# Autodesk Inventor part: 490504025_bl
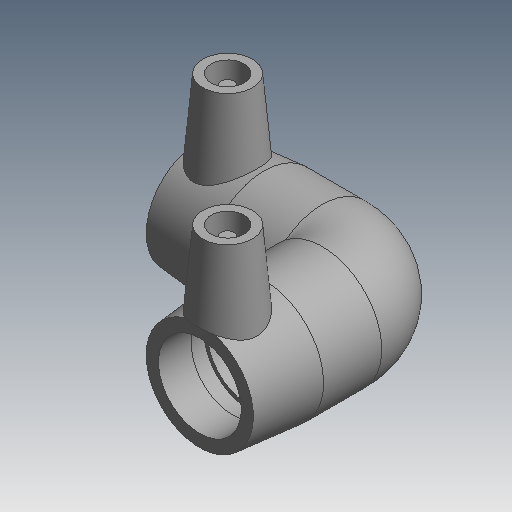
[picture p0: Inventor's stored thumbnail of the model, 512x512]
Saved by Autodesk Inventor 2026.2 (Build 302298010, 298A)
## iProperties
Created: 2017-06
Part Number: 490504025_bl
Material: Generic
Description: PLASSON 90° ELBOW 25
Document SubType Name: Modeling
Designer: KIM
Mass: 55.0731 g
Surface Area: 148.067 cm^2
Volume: 55.0731 cm^3
Density: 1 g/cm^3
Appearance: Default
Author: KIM
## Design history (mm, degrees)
derived "490504 -20-75.ipt"
feature "Solid1::490504 -20-75.ipt" dims "ScaleForDerivedMember" = 10
tag "TaggingFeature1"
body "Solid1"
other parameters: "d2" = 36 [user parameter], "d4" = 19.41176 [user parameter], "d5" = 32.4 [user parameter], "d8" = 168 deg [user parameter], "d10" = 14.8 [user parameter], "d11" = 4.93333 [user parameter], "d14" = 17.6296 [user parameter], "d18" = 25 [user parameter], "d19" = 3.52592 [user parameter], "d20" = 168 deg [user parameter], "d22" = 33.12 [user parameter], "d23" = 36 [user parameter], "d24" = 32.1264 [user parameter], "d29" = 38 [user parameter], "d30" = 15 [user parameter], "d31" = 39.6 [user parameter], "d34" = 5 deg [user parameter], "d35" = 15 [user parameter], "d39" = 5 deg [user parameter], "d41" = 4 [user parameter], "d42" = 14 [user parameter], "d43" = 0 [user parameter], "d45" = 4 [user parameter], "d46" = 14 [user parameter], "d47" = 0 [user parameter], "d49" = 25 [user parameter], "d50" = 21.25 [user parameter], "d51" = 14.8 [user parameter], "d52" = 37 [user parameter], "d54" = 90 deg [user parameter], "d65" = 25 [user parameter], "d67" = 45 deg [user parameter], "d71" = 90 deg [user parameter], "d75" = 1.8 [user parameter], "d82" = 45 deg [user parameter], "d83" = 37 [user parameter], "d84" = 32.4 [user parameter], "d87" = 90 deg [user parameter], "d90" = 37 [user parameter], "d91" = 0 [user parameter], "d92" = 37 [user parameter], "d93" = 0 [user parameter], "d94" = 90 deg [user parameter], "d101" = 3 [user parameter], "d102" = 0 [user parameter], "d103" = 3 [user parameter], "d104" = 0 [user parameter], "d105" = 10.73 [user parameter], "d106" = 2.6825 [user parameter], "d110" = 20.35 [user parameter], "d111" = 66 [user parameter], "d112" = 66 [user parameter], "d113" = 66 [user parameter], "d114" = 66 [user parameter], "d_" = 25 [user parameter], "L_" = 66 [user parameter], "L_1" = 37 [user parameter], "D_" = 36 [user parameter], "A_" = 38 [user parameter], "d_2" = 12 [user parameter]
